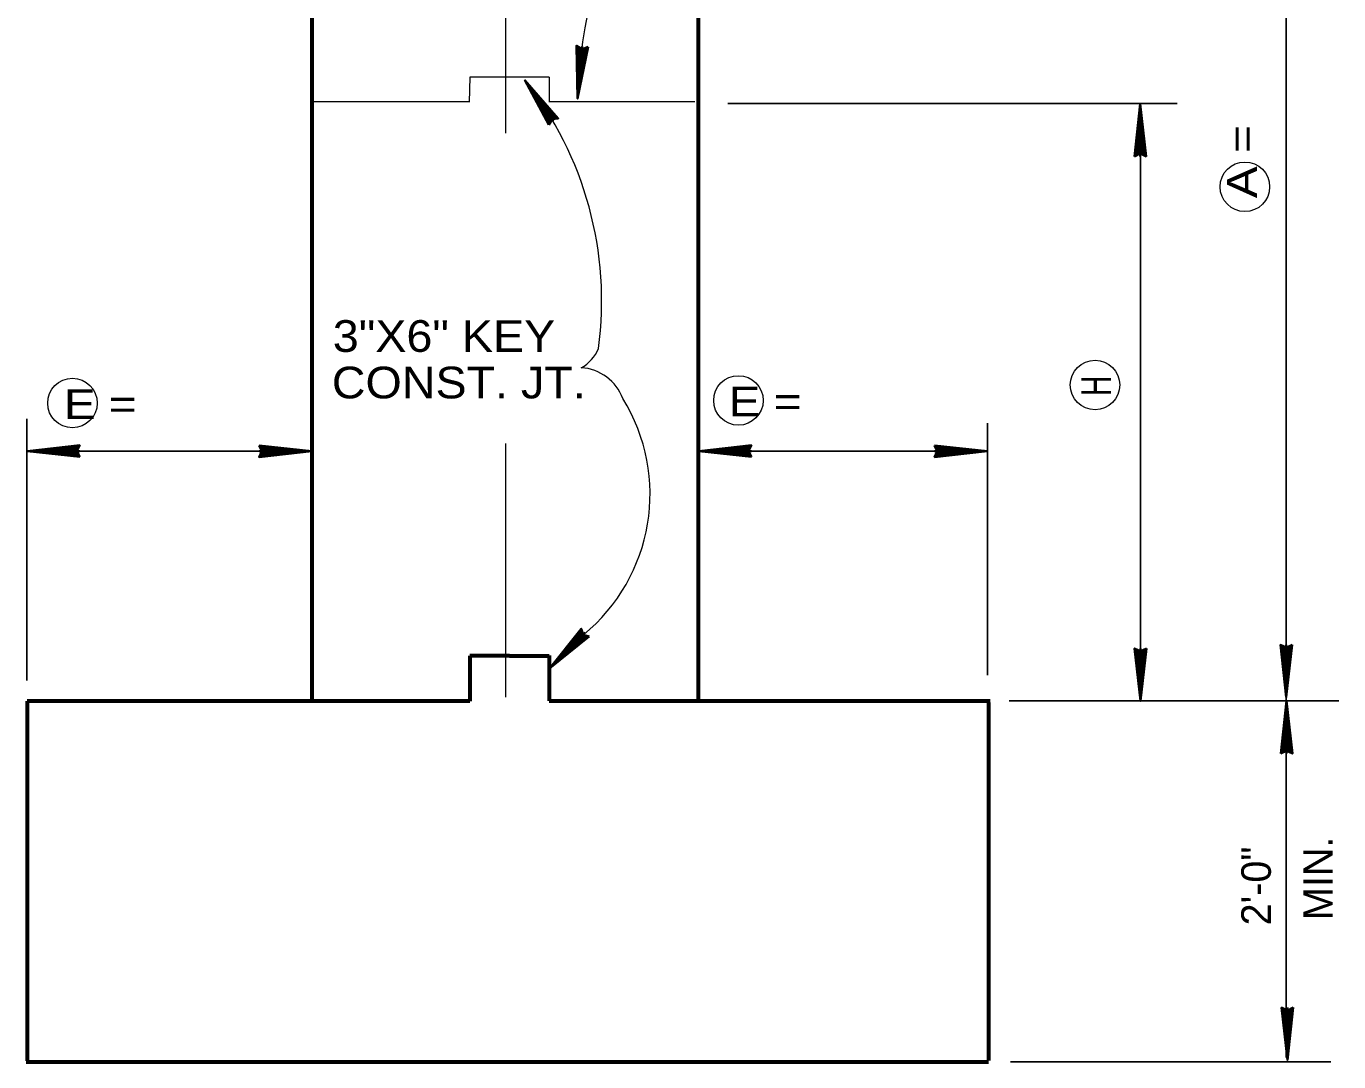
# Model space of a CAD drawing. Extents: x 1.6 to 19.9, y 2.8 to 9.5.
# Drawn here: x 17.727 to 18.244, y 7.72 to 8.128 of the extents above; entities that cross this region are included whole.
import ezdxf
from ezdxf.enums import TextEntityAlignment as Align

# ---------------------------------------------------------------- set-up
doc = ezdxf.new("R2010")
doc.units = 0
doc.header["$LTSCALE"] = 0.0047
doc.linetypes.add('DOT_DASHED', pattern=[7.7, 5, -1.2, 0.3, -1.2])
doc.linetypes.add('LONG_DASHED', pattern=[7.5, 6, -1.5])
doc.layers.add('1', color=7, linetype='Continuous', lineweight=35)
doc.layers.add('5', color=7, linetype='Continuous', lineweight=13)

msp = doc.modelspace()

# ---------------------------------------------------------------- linework, layer by layer
at = {"layer": '1', "lineweight": 60}
for p, q in [((17.839583, 7.862833), (17.839583, 8.33525)), ((17.991833, 7.86225), (17.991833, 8.33525)), ((17.91725, 7.87975), (17.901667, 7.87975)), ((17.901667, 7.87975), (17.901667, 7.861917)), ((17.91725, 7.87975), (17.932917, 7.87975)), ((17.932917, 7.879833), (17.932917, 7.862)), ((17.727167, 7.862), (17.901667, 7.862)), ((17.727167, 7.861917), (17.727167, 7.720083)), ((17.932917, 7.862), (18.106833, 7.862)), ((18.106167, 7.861333), (18.106167, 7.72025)), ((17.726833, 7.71975), (18.106167, 7.71975))]:
    msp.add_line(p, q, dxfattribs=at)
at = {"layer": '1', "lineweight": 25}
for p, q in [((18.2235, 8.335667), (18.2235, 7.721417)), ((18.003417, 8.0975), (18.180417, 8.0975)), ((18.166, 8.09625), (18.166, 7.86225)), ((17.727083, 7.97325), (17.727083, 7.879417)), ((18.10575, 7.9715), (18.10575, 7.872167)), ((17.727667, 7.960417), (17.836667, 7.960417)), ((17.99425, 7.960417), (18.10325, 7.960417)), ((17.727083, 7.879417), (17.727083, 7.870083)), ((17.83975, 7.86325), (17.83975, 7.86275)), ((17.992, 7.86325), (17.992, 7.86275)), ((18.11425, 7.862), (18.244167, 7.862)), ((18.114833, 7.71975), (18.241083, 7.71975))]:
    msp.add_line(p, q, dxfattribs=at)
at = {"layer": '1'}
for p, q in [((17.943917, 8.119833), (17.944333, 8.105333)), ((17.946, 8.12), (17.944167, 8.099417)), ((17.944167, 8.11975), (17.9445, 8.10525)), ((17.944417, 8.11975), (17.94475, 8.105333)), ((17.947583, 8.1195), (17.944583, 8.104333)), ((17.944667, 8.11975), (17.945083, 8.105417)), ((17.947667, 8.1195), (17.944667, 8.104333)), ((17.948, 8.1195), (17.944917, 8.10425)), ((17.947917, 8.1195), (17.944917, 8.10425)), ((17.947917, 8.1195), (17.944917, 8.10425)), ((17.934667, 8.0905), (17.923417, 8.106667)), ((17.932917, 8.089667), (17.92575, 8.102667)), ((17.93275, 8.089667), (17.92575, 8.102583)), ((17.933083, 8.089833), (17.925833, 8.10275)), ((17.932917, 8.089667), (17.925917, 8.10275)), ((17.93325, 8.089917), (17.926, 8.103)), ((17.9355, 8.091417), (17.926417, 8.101833)), ((17.935667, 8.0915), (17.926583, 8.102083)), ((17.935917, 8.092), (17.92675, 8.102333)), ((17.935917, 8.091667), (17.92675, 8.102083)), ((18.165917, 8.076667), (18.165917, 8.097333)), ((18.163917, 8.077), (18.165667, 8.0925)), ((18.164, 8.077), (18.16575, 8.0925)), ((18.164167, 8.077), (18.165833, 8.0925)), ((18.164333, 8.077), (18.166083, 8.0925)), ((18.164667, 8.077667), (18.166333, 8.093083)), ((18.16725, 8.077), (18.165667, 8.091333)), ((18.167417, 8.077), (18.165917, 8.091417)), ((18.167667, 8.077), (18.166167, 8.0915)), ((18.167917, 8.077167), (18.166333, 8.0915)), ((17.747417, 7.962333), (17.733, 7.96075)), ((17.747417, 7.96225), (17.733, 7.960667)), ((17.747417, 7.962), (17.733083, 7.960417)), ((17.818917, 7.962333), (17.8345, 7.960667)), ((17.818917, 7.96225), (17.8345, 7.960583)), ((17.818917, 7.96225), (17.8345, 7.9605)), ((17.818917, 7.962), (17.8345, 7.96025)), ((17.819, 7.9625), (17.8345, 7.96075)), ((18.012167, 7.962333), (17.99775, 7.96075)), ((18.012167, 7.96225), (17.99775, 7.960667)), ((18.01225, 7.962), (17.997917, 7.960417)), ((18.085167, 7.962333), (18.10075, 7.960667)), ((18.085167, 7.96225), (18.10075, 7.960583)), ((18.085167, 7.96225), (18.10075, 7.9605)), ((18.085167, 7.962), (18.10075, 7.96025)), ((18.08525, 7.9625), (18.10075, 7.96075)), ((17.747917, 7.960417), (17.727167, 7.960417)), ((17.747417, 7.9585), (17.732, 7.960167)), ((17.747417, 7.9585), (17.732, 7.960167)), ((17.747417, 7.958417), (17.732, 7.960083)), ((17.747417, 7.958833), (17.732083, 7.9605)), ((17.747417, 7.958583), (17.732083, 7.960333)), ((17.747417, 7.96175), (17.733083, 7.960167)), ((17.818583, 7.960417), (17.839417, 7.960417)), ((17.818917, 7.959083), (17.833417, 7.960667)), ((17.818917, 7.958833), (17.833417, 7.960417)), ((17.818917, 7.958583), (17.8335, 7.960167)), ((17.819, 7.958417), (17.8335, 7.96)), ((18.012667, 7.960417), (17.991917, 7.960417)), ((18.012167, 7.9585), (17.99675, 7.960167)), ((18.012167, 7.9585), (17.99675, 7.960167)), ((18.012167, 7.958417), (17.99675, 7.960083)), ((18.01225, 7.958833), (17.996833, 7.9605)), ((18.012167, 7.958583), (17.996833, 7.960333)), ((18.01225, 7.96175), (17.997917, 7.960167)), ((18.084833, 7.960417), (18.105667, 7.960417)), ((18.085167, 7.959083), (18.099667, 7.960667)), ((18.085167, 7.958833), (18.099667, 7.960417)), ((18.085167, 7.958583), (18.09975, 7.960167)), ((18.08525, 7.958417), (18.09975, 7.96)), ((17.9455, 7.88975), (17.936917, 7.879167)), ((17.945667, 7.88975), (17.937, 7.878917)), ((17.945833, 7.889667), (17.937167, 7.878833)), ((17.946083, 7.889583), (17.937333, 7.878833)), ((17.947083, 7.888917), (17.933083, 7.874833)), ((17.947833, 7.887583), (17.936417, 7.87825)), ((17.94825, 7.88725), (17.936583, 7.878)), ((17.948167, 7.88725), (17.936583, 7.878)), ((17.948, 7.887333), (17.936667, 7.878167)), ((17.948167, 7.88725), (17.936667, 7.878167)), ((18.164, 7.88225), (18.165667, 7.867833)), ((18.16425, 7.88225), (18.165833, 7.867833)), ((18.1645, 7.88225), (18.166083, 7.867917)), ((18.16475, 7.88225), (18.166417, 7.868)), ((18.166, 7.882667), (18.166, 7.862)), ((18.167667, 7.88225), (18.166, 7.866917)), ((18.16775, 7.88225), (18.166083, 7.866917)), ((18.167917, 7.88225), (18.166333, 7.866833)), ((18.168083, 7.88225), (18.166417, 7.866833)), ((18.168, 7.88225), (18.166417, 7.866833)), ((18.2215, 7.88375), (18.223167, 7.86925)), ((18.22175, 7.88375), (18.223333, 7.86925)), ((18.222, 7.88375), (18.223583, 7.869333)), ((18.22225, 7.88375), (18.223917, 7.869417)), ((18.2235, 7.884083), (18.2235, 7.863417)), ((18.225167, 7.88375), (18.2235, 7.86825)), ((18.22525, 7.88375), (18.223583, 7.86825)), ((18.225417, 7.88375), (18.223833, 7.86825)), ((18.225583, 7.88375), (18.223917, 7.86825)), ((18.2255, 7.88375), (18.223917, 7.86825)), ((18.223583, 7.84125), (18.223583, 7.862)), ((18.221667, 7.84175), (18.22325, 7.857167)), ((18.221667, 7.841667), (18.223333, 7.857167)), ((18.221667, 7.841667), (18.223417, 7.857167)), ((18.221833, 7.841667), (18.2235, 7.857)), ((18.222, 7.841667), (18.223667, 7.857)), ((18.224917, 7.841583), (18.223333, 7.856)), ((18.225167, 7.841667), (18.223583, 7.856)), ((18.225417, 7.841667), (18.223833, 7.856083)), ((18.225583, 7.84175), (18.223917, 7.856083)), ((18.221917, 7.74075), (18.223583, 7.72625)), ((18.222167, 7.74075), (18.223667, 7.72625)), ((18.222417, 7.74075), (18.223917, 7.726333)), ((18.222667, 7.74075), (18.22425, 7.726417)), ((18.223917, 7.741083), (18.223917, 7.720417)), ((18.225667, 7.74075), (18.223917, 7.725333)), ((18.2255, 7.74075), (18.223917, 7.725333)), ((18.225833, 7.74075), (18.224167, 7.72525)), ((18.226, 7.74075), (18.22425, 7.72525)), ((18.225917, 7.74075), (18.22425, 7.72525))]:
    msp.add_line(p, q, dxfattribs=at)
at = {"layer": '1', "linetype": 'LONG_DASHED', "lineweight": 13}
for p, q in [((17.932917, 8.107917), (17.932917, 8.098)), ((17.901167, 8.098167), (17.8395, 8.098167)), ((17.990417, 8.098167), (17.932917, 8.098167))]:
    msp.add_line(p, q, dxfattribs=at)
at = {"layer": '1'}
for points in [[(17.948333, 8.119833), (17.944167, 8.099417), (17.943667, 8.12025), (17.946, 8.118917)], [(17.946167, 8.118583), (17.945417, 8.1095), (17.945167, 8.1095), (17.945583, 8.11125)], [(17.932833, 8.089083), (17.923417, 8.106667), (17.9365, 8.091583), (17.934167, 8.091333)], [(18.163667, 8.076667), (18.165917, 8.097333), (18.16825, 8.076667), (18.165917, 8.07775)], [(17.747917, 7.958167), (17.727167, 7.960417), (17.747917, 7.96275), (17.74675, 7.960417)], [(17.818583, 7.962667), (17.839417, 7.960417), (17.818583, 7.958083), (17.819667, 7.960417)], [(18.012667, 7.958167), (17.991917, 7.960417), (18.012667, 7.96275), (18.0115, 7.960417)], [(18.084833, 7.962667), (18.105667, 7.960417), (18.084833, 7.958083), (18.085917, 7.960417)], [(17.746417, 7.960167), (17.73725, 7.96), (17.73725, 7.96025), (17.739, 7.960167), (17.746417, 7.96), (17.7405, 7.959833), (17.746667, 7.95975), (17.742333, 7.9595), (17.746833, 7.959333), (17.739833, 7.959833), (17.730583, 7.96025), (17.732417, 7.96075), (17.729917, 7.960583), (17.746417, 7.960667), (17.741667, 7.961), (17.746667, 7.961), (17.736167, 7.960167), (17.74675, 7.961333)], [(18.011167, 7.960167), (18.002, 7.96), (18.002, 7.96025), (18.003833, 7.960167), (18.011167, 7.96), (18.00525, 7.959833), (18.011417, 7.95975), (18.007083, 7.9595), (18.011667, 7.959333), (18.004583, 7.959833), (17.995417, 7.96025), (17.99725, 7.96075), (17.99475, 7.960583), (18.011167, 7.960667), (18.006417, 7.961), (18.011417, 7.961), (18.000917, 7.960167), (18.0115, 7.961333)], [(17.948667, 7.887417), (17.933083, 7.874833), (17.945583, 7.890417), (17.946417, 7.888083)], [(17.94625, 7.88775), (17.940333, 7.881417), (17.940083, 7.881583), (17.941333, 7.882667), (17.946417, 7.887667), (17.942667, 7.883417), (17.947, 7.887583), (17.944, 7.884583), (17.947167, 7.887583), (17.942, 7.883), (17.935667, 7.877167), (17.936667, 7.87875), (17.935083, 7.876833), (17.946083, 7.887833), (17.942583, 7.884917), (17.946, 7.8885), (17.939333, 7.880833), (17.945917, 7.888917)], [(18.168333, 7.882667), (18.166, 7.862), (18.163667, 7.882667), (18.166083, 7.881583)], [(18.166417, 7.88125), (18.166417, 7.872), (18.166167, 7.872167), (18.166417, 7.873833)], [(18.225833, 7.884083), (18.2235, 7.863417), (18.221167, 7.884083), (18.223583, 7.883)], [(18.223917, 7.882667), (18.223917, 7.8735), (18.223667, 7.8735), (18.223917, 7.87525)], [(18.221333, 7.84125), (18.223583, 7.862), (18.225917, 7.84125), (18.223583, 7.842333)], [(18.226167, 7.741083), (18.223917, 7.720417), (18.221667, 7.741083), (18.223917, 7.74)], [(18.22425, 7.73975), (18.22425, 7.7305), (18.224, 7.730583), (18.22425, 7.73225)]]:
    msp.add_lwpolyline(points, close=True, dxfattribs=at)
for points in [[(17.946167, 8.118583), (17.946083, 8.112667), (17.9465, 8.118917), (17.946417, 8.1145), (17.947, 8.119), (17.945917, 8.112), (17.944583, 8.102833), (17.944333, 8.104833), (17.944333, 8.10225), (17.945667, 8.11875), (17.944917, 8.113917), (17.945417, 8.119), (17.94525, 8.108417), (17.944917, 8.119167), (17.946167, 8.1185), (17.947667, 8.119417), (17.947333, 8.118917), (17.946417, 8.1185), (17.946667, 8.118083), (17.947333, 8.11825), (17.945833, 8.11875), (17.944917, 8.119333), (17.944, 8.119833)], [(17.93375, 8.09125), (17.928583, 8.098583), (17.928667, 8.098667), (17.929667, 8.09725), (17.933667, 8.091333), (17.93, 8.095833), (17.933417, 8.091), (17.931, 8.094167), (17.933333, 8.0905), (17.929833, 8.0965), (17.925083, 8.10375), (17.926583, 8.1025), (17.924917, 8.104667), (17.934083, 8.091667), (17.931667, 8.095667), (17.934333, 8.091583), (17.928083, 8.0995), (17.934833, 8.091833), (17.933833, 8.091417), (17.933083, 8.090083), (17.933083, 8.0905), (17.9335, 8.091333), (17.932917, 8.0915), (17.93275, 8.091), (17.934, 8.091417), (17.934917, 8.091583), (17.935917, 8.091833)], [(18.165667, 8.078083), (18.1655, 8.08725), (18.165833, 8.08725), (18.165667, 8.0855), (18.1655, 8.078083), (18.165417, 8.084), (18.165167, 8.077833), (18.165167, 8.082167), (18.164917, 8.077583), (18.165417, 8.08475), (18.165833, 8.093917), (18.166333, 8.092), (18.166083, 8.0945), (18.166167, 8.078083), (18.166417, 8.082917), (18.166417, 8.077833), (18.16575, 8.088417), (18.166833, 8.077667), (18.16575, 8.078167), (18.16425, 8.07725), (18.164583, 8.077667), (18.165417, 8.078167), (18.165167, 8.078583), (18.1645, 8.07825), (18.166, 8.078), (18.166833, 8.077583), (18.167917, 8.077167)], [(17.746417, 7.960167), (17.74725, 7.95875), (17.74675, 7.959083), (17.746417, 7.959833), (17.745833, 7.959667), (17.746167, 7.959), (17.7465, 7.9605), (17.746917, 7.961333), (17.747417, 7.962333)], [(17.819917, 7.960667), (17.82925, 7.96075), (17.829167, 7.960583), (17.827417, 7.960667), (17.819917, 7.96075), (17.826, 7.961), (17.81975, 7.961083), (17.824, 7.96125), (17.8195, 7.9615), (17.826667, 7.961), (17.835917, 7.960583), (17.834, 7.96), (17.836667, 7.96025), (17.819917, 7.960167), (17.824833, 7.959833), (17.81975, 7.959833), (17.83025, 7.960583), (17.819583, 7.9595), (17.820083, 7.960583), (17.819167, 7.962), (17.819583, 7.96175), (17.820083, 7.961), (17.8205, 7.96125), (17.820167, 7.961833), (17.819833, 7.960333), (17.819417, 7.9595), (17.819, 7.9585)], [(18.011167, 7.960167), (18.012, 7.95875), (18.0115, 7.959083), (18.011167, 7.959833), (18.010583, 7.959667), (18.011, 7.959), (18.011333, 7.9605), (18.011667, 7.961333), (18.012167, 7.962333)], [(18.086167, 7.960667), (18.0955, 7.96075), (18.095417, 7.960583), (18.093667, 7.960667), (18.086167, 7.96075), (18.09225, 7.961), (18.086, 7.961083), (18.09025, 7.96125), (18.08575, 7.9615), (18.092917, 7.961), (18.102167, 7.960583), (18.10025, 7.96), (18.102917, 7.96025), (18.086167, 7.960167), (18.091083, 7.959833), (18.086, 7.959833), (18.0965, 7.960583), (18.085833, 7.9595), (18.086333, 7.960583), (18.085417, 7.962), (18.085833, 7.96175), (18.086333, 7.961), (18.08675, 7.96125), (18.086417, 7.961833), (18.086083, 7.960333), (18.085667, 7.9595), (18.08525, 7.9585)], [(17.94625, 7.88775), (17.947917, 7.887417), (17.947417, 7.887167), (17.946583, 7.8875), (17.946417, 7.887), (17.947, 7.886833), (17.946417, 7.888), (17.945917, 7.888917), (17.9455, 7.88975)], [(18.166417, 7.88125), (18.166667, 7.875333), (18.166667, 7.881583), (18.166833, 7.87725), (18.167083, 7.88175), (18.166667, 7.874667), (18.166167, 7.865417), (18.165667, 7.867333), (18.165917, 7.86475), (18.165833, 7.88125), (18.1655, 7.8765), (18.1655, 7.881583), (18.166333, 7.871), (18.165083, 7.881667), (18.166333, 7.88125), (18.167667, 7.882167), (18.167417, 7.881667), (18.166667, 7.88125), (18.16675, 7.88075), (18.167417, 7.881), (18.166, 7.881333), (18.165083, 7.881833), (18.164167, 7.88225)], [(18.223917, 7.882667), (18.224167, 7.87675), (18.224167, 7.883), (18.224333, 7.878583), (18.224583, 7.883167), (18.224167, 7.876), (18.223667, 7.866833), (18.223167, 7.86875), (18.223417, 7.86625), (18.223333, 7.882667), (18.223, 7.877917), (18.223, 7.883), (18.223833, 7.872333), (18.222583, 7.883083), (18.223833, 7.882583), (18.225167, 7.8835), (18.224917, 7.883083), (18.224167, 7.882583), (18.22425, 7.882167), (18.224917, 7.8825), (18.2235, 7.88275), (18.222583, 7.88325), (18.221667, 7.88375)], [(18.223333, 7.842667), (18.223167, 7.851917), (18.2235, 7.851833), (18.223333, 7.850083), (18.223167, 7.842667), (18.223, 7.848583), (18.222917, 7.8425), (18.22275, 7.84675), (18.222583, 7.84225), (18.223, 7.849333), (18.2235, 7.8585), (18.223917, 7.856583), (18.223667, 7.859167), (18.223833, 7.842667), (18.224167, 7.8475), (18.224167, 7.8425), (18.223417, 7.853), (18.2245, 7.84225), (18.223417, 7.84275), (18.221917, 7.841833), (18.22225, 7.84225), (18.223, 7.84275), (18.222917, 7.84325), (18.222167, 7.842917), (18.223667, 7.842583), (18.2245, 7.84225), (18.2255, 7.84175)], [(18.22425, 7.73975), (18.224583, 7.73375), (18.224583, 7.74), (18.22475, 7.735667), (18.224917, 7.740167), (18.2245, 7.733083), (18.224, 7.723833), (18.223583, 7.72575), (18.223833, 7.72325), (18.223667, 7.73975), (18.223417, 7.735), (18.223417, 7.74), (18.224167, 7.729417), (18.222917, 7.740083), (18.224167, 7.739667), (18.225583, 7.740583), (18.22525, 7.740083), (18.2245, 7.739667), (18.224667, 7.739167), (18.225417, 7.7395), (18.223917, 7.73975), (18.222917, 7.74025), (18.222, 7.74075)]]:
    msp.add_lwpolyline(points, dxfattribs=at)
at = {"layer": '1', "linetype": 'LONG_DASHED', "lineweight": 13}
msp.add_lwpolyline([(17.932917, 8.107917), (17.901667, 8.107917), (17.901417, 8.098083)], dxfattribs=at)
at = {"layer": '1', "lineweight": 13}
for centre in [(18.20716, 8.064654), (18.148098, 7.986529), (17.745051, 7.979419), (18.007551, 7.980435)]:
    msp.add_circle(centre, 0.009766, dxfattribs=at)
for centre, radius, start, end in [((18.124414, 8.095025), 0.180294, 122.06338, 178.61588), ((17.813864, 8.019882), 0.139762, 352.20117, 38.38546), ((17.938567, 8.006374), 0.014808, 298.28025, 338.37456), ((17.944454, 7.97465), 0.018717, 20.37464, 86.53984), ((17.901069, 7.943516), 0.071626, 309.31877, 31.71279)]:
    msp.add_arc(centre, radius, start, end, dxfattribs=at)
at = {"layer": '5', "linetype": 'DOT_DASHED'}
for p, q in [((17.91575, 8.38575), (17.91575, 8.03225)), ((17.91575, 7.963417), (17.91575, 7.81625))]:
    msp.add_line(p, q, dxfattribs=at)

# ---------------------------------------------------------------- texts
at = {"layer": '1', "width": 0.7}
msp.add_text('H', height=0.01167, rotation=90, dxfattribs=at).set_placement((18.154333, 7.986208), align=Align.CENTER)
at = {"layer": '1'}
msp.add_text('2\'-0"', height=0.01167, rotation=90, dxfattribs=at).set_placement((18.217417, 7.7735))
at = {"layer": '5', "width": 1.2}
msp.add_text('A =      ', height=0.01175, rotation=90, dxfattribs=at).set_placement((18.211917, 8.060167))
at = {"layer": '5', "width": 1.1}
for s, p in [('3"X6" KEY', (17.8915, 7.999583)), ('CONST. JT.', (17.897333, 7.98125))]:
    msp.add_text(s, height=0.0125, dxfattribs=at).set_placement(p, align=Align.CENTER)
at = {"layer": '5', "width": 1.2}
for height, p in [(0.01167, (17.741667, 7.973167)), (0.01175, (18.003667, 7.974167))]:
    msp.add_text('E =      ', height=height, dxfattribs=at).set_placement(p)
at = {"layer": '5'}
msp.add_text('MIN.', height=0.01167, rotation=90, dxfattribs=at).set_placement((18.241833, 7.775583))

doc.saveas('drawing.dxf')
